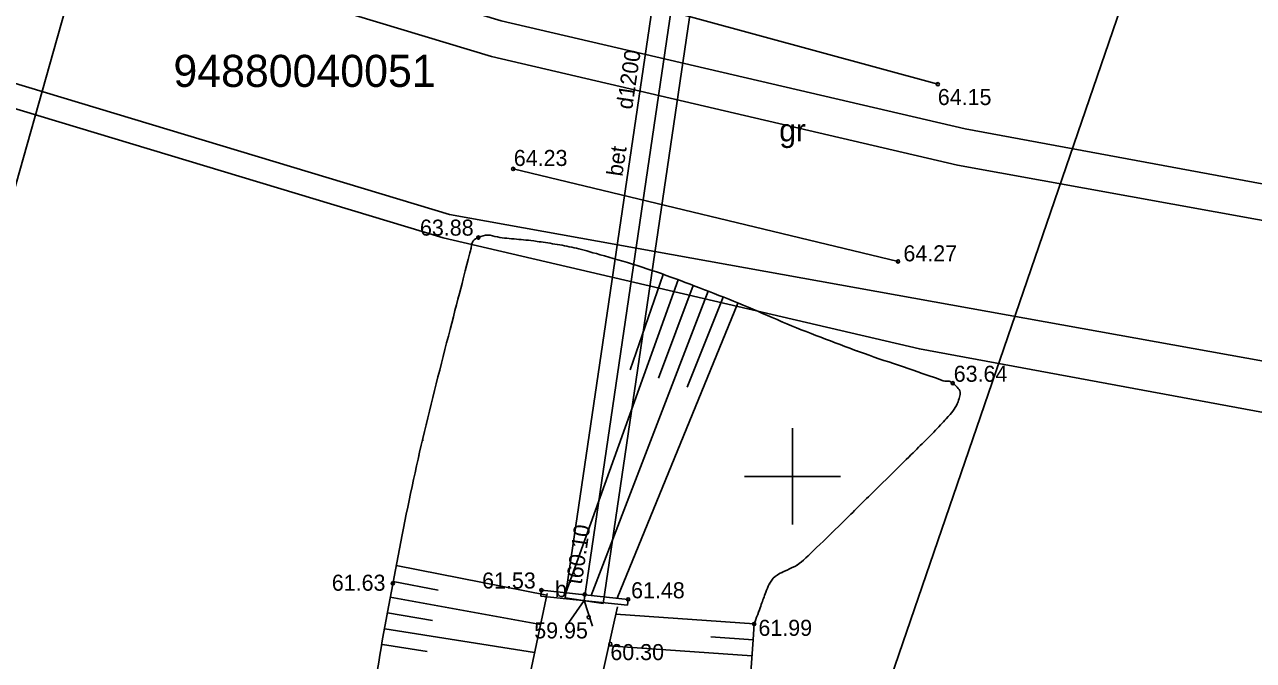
# Model space of a CAD drawing. Extents: x 616607 to 617499, y 408385 to 409695.
# Drawn here: x 617176.04 to 617214.38, y 409044.26 to 409064.08 of the extents above; entities that cross this region are included whole.
import ezdxf

# ---------------------------------------------------------------- set-up
doc = ezdxf.new("R2010")
doc.units = 0
for name, color, linetype in [('BUVE_BDET_####_####_#', 7, 'Continuous'), ('BUVE_BDET_####_TKST_#', 7, 'Continuous'), ('BUVE_INZE_VEKT_####_#', 7, 'Continuous'), ('CELI_CSEG_####_TKST_#', 7, 'Continuous'), ('CELI_TAKA_####_####_#', 7, 'Continuous'), ('GEOD_ELEM_####_####_#', 7, 'Continuous'), ('HIDG_GRAV_####_####_#', 7, 'Continuous'), ('HIDT_CAUR_####_####_#', 7, 'Continuous'), ('HIDT_CAUR_####_TKST_#', 7, 'Continuous'), ('HIDT_CAUR_KONT_####_#', 7, 'Continuous'), ('HIDT_ELEM_####_####_#', 7, 'Continuous'), ('RAMI_UZMR_####_####_#', 7, 'Continuous'), ('RELJ_AATZ_####_TKST_#', 7, 'Continuous'), ('RELJ_ELEM_####_####_#', 7, 'Continuous'), ('RELJ_NOGA_####_####_#', 7, 'Continuous'), ('ROBZ_IERR_####_####_#', 7, 'Continuous'), ('ROBZ_PROJ_####_####_#', 7, 'Continuous'), ('ROBZ_PROJ_####_TKST_#', 7, 'Continuous')]:
    doc.layers.add(name, color=color, linetype=linetype)

# ---------------------------------------------------------------- blocks, each defined once
blk = doc.blocks.new('PKT')
at = {"layer": 'RELJ_ELEM_####_####_#'}
blk.add_circle((0, 0), 0.05, dxfattribs=at)
blk = doc.blocks.new('CAURT')
at = {"layer": 'HIDT_ELEM_####_####_#'}
blk.add_lwpolyline([(0.75, -0.374), (0, 0), (0.75, 0.376)], dxfattribs=at)
blk = doc.blocks.new('KRUSTS')
at = {"layer": 'GEOD_ELEM_####_####_#'}
for p, q in [((0, 1.5), (0, 0)), ((-1.5, 0), (0, 0)), ((0, 0), (0, -1.5)), ((0, 0), (1.5, 0))]:
    blk.add_line(p, q, dxfattribs=at)

msp = doc.modelspace()

# ---------------------------------------------------------------- linework, layer by layer
at = {"layer": 'BUVE_BDET_####_####_#'}
for p, q in [((617192.148, 409046.271), (617192.167, 409046.451)), ((617192.148, 409046.271), (617194.853, 409045.986)), ((617194.853, 409045.986), (617194.872, 409046.167))]:
    msp.add_line(p, q, dxfattribs=at)
msp.add_lwpolyline([(617192.167, 409046.451), (617194.872, 409046.167)], dxfattribs=at)
at = {"layer": 'BUVE_INZE_VEKT_####_#'}
for points in [[(617176.359, 409067.385), (617190.61, 409063.088), (617205.141, 409059.702), (617231.897, 409054.857)], [(617230.443, 409050.755), (617189.294, 409058.158), (617174.515, 409062.614)]]:
    msp.add_lwpolyline(points, dxfattribs=at)
at = {"layer": 'CELI_TAKA_####_####_#'}
for points in [[(617193.303, 409065.287), (617204.53, 409062.221)], [(617203.29, 409056.699), (617191.285, 409059.581)]]:
    msp.add_lwpolyline(points, dxfattribs=at)
at = {"layer": 'HIDG_GRAV_####_####_#'}
for points in [[(617165.749, 408966.38), (617185.985, 409016.335), (617192.341, 409046.347)], [(617167.163, 408965.849), (617187.78, 409015.761), (617194.535, 409045.934)]]:
    msp.add_lwpolyline(points, dxfattribs=at)
at = {"layer": 'HIDT_CAUR_####_####_#'}
msp.add_lwpolyline([(617193.501, 409046.129), (617197.36, 409072.314)], dxfattribs=at)
at = {"layer": 'HIDT_CAUR_KONT_####_#'}
for p, q in [((617192.907, 409046.216), (617196.767, 409072.401)), ((617194.094, 409046.041), (617197.954, 409072.226))]:
    msp.add_line(p, q, dxfattribs=at)
msp.add_lwpolyline([(617192.907, 409046.216), (617194.094, 409046.041)], dxfattribs=at)
at = {"layer": 'RAMI_UZMR_####_####_#'}
msp.add_lwpolyline([(617101.571, 408748.246), (617213.472, 409074.039), (617215.883, 409140.56), (617165.121, 409241.478), (617252.137, 409353.424), (617269.572, 409425.099), (617332.631, 409510.312), (617439.945, 409622.037), (617425.373, 409635.959), (617242.079, 409440.82), (617216.614, 409355.716), (617136.613, 409246.751), (617191.828, 409115.62), (617145.545, 408952.8)], dxfattribs=at)
at = {"layer": 'RELJ_NOGA_####_####_#'}
for p, q in [((617190.611, 409057.487), (617190.611, 409057.488)), ((617190.611, 409057.487), (617190.611, 409057.486)), ((617190.128, 409057.401), (617190.128, 409057.402)), ((617190.128, 409057.401), (617190.128, 409057.401)), ((617191.106, 409057.417), (617191.106, 409057.418)), ((617191.106, 409057.417), (617191.106, 409057.417)), ((617191.604, 409057.371), (617191.604, 409057.372)), ((617191.604, 409057.371), (617191.604, 409057.37)), ((617192.1, 409057.311), (617192.1, 409057.311)), ((617192.1, 409057.311), (617192.1, 409057.311)), ((617192.594, 409057.233), (617192.594, 409057.234)), ((617192.594, 409057.233), (617192.594, 409057.232)), ((617193.085, 409057.139), (617193.085, 409057.139)), ((617193.085, 409057.139), (617193.085, 409057.138)), ((617189.934, 409056.95), (617189.933, 409056.951)), ((617189.934, 409056.95), (617189.935, 409056.95)), ((617193.572, 409057.025), (617193.571, 409057.024)), ((617193.572, 409057.025), (617193.572, 409057.026)), ((617194.054, 409056.892), (617194.053, 409056.891)), ((617194.054, 409056.892), (617194.054, 409056.892)), ((617194.533, 409056.75), (617194.533, 409056.751)), ((617194.533, 409056.75), (617194.533, 409056.749)), ((617189.808, 409056.467), (617189.808, 409056.466)), ((617189.808, 409056.467), (617189.808, 409056.467)), ((617195.011, 409056.602), (617195.011, 409056.602)), ((617195.011, 409056.602), (617195.011, 409056.602)), ((617195.486, 409056.447), (617195.486, 409056.448)), ((617195.486, 409056.447), (617195.486, 409056.446)), ((617195.959, 409056.286), (617195.96, 409056.287)), ((617189.683, 409055.982), (617189.682, 409055.983)), ((617189.683, 409055.982), (617189.684, 409055.982)), ((617196.431, 409056.12), (617192.927, 409046.371)), ((617195.959, 409056.286), (617194.937, 409053.324)), ((617196.9, 409055.947), (617195.819, 409053.063)), ((617196.431, 409056.12), (617196.431, 409056.121)), ((617196.9, 409055.947), (617196.9, 409055.948)), ((617197.368, 409055.77), (617193.722, 409046.288)), ((617197.833, 409055.587), (617196.71, 409052.785)), ((617197.368, 409055.77), (617197.368, 409055.771)), ((617197.833, 409055.587), (617197.833, 409055.587)), ((617189.558, 409055.498), (617189.559, 409055.498)), ((617189.558, 409055.498), (617189.558, 409055.498)), ((617198.296, 409055.398), (617194.527, 409046.203)), ((617198.296, 409055.398), (617198.296, 409055.399)), ((617198.758, 409055.207), (617198.758, 409055.207)), ((617198.758, 409055.207), (617198.758, 409055.207)), ((617189.434, 409055.014), (617189.433, 409055.014)), ((617189.434, 409055.014), (617189.435, 409055.014)), ((617199.219, 409055.014), (617199.22, 409055.015)), ((617199.219, 409055.014), (617199.219, 409055.013)), ((617199.681, 409054.821), (617199.68, 409054.821)), ((617199.681, 409054.821), (617199.681, 409054.821)), ((617189.311, 409054.529), (617189.312, 409054.529)), ((617189.311, 409054.529), (617189.311, 409054.529)), ((617200.143, 409054.631), (617200.142, 409054.63)), ((617200.143, 409054.631), (617200.143, 409054.631)), ((617200.607, 409054.443), (617200.606, 409054.443)), ((617200.607, 409054.443), (617200.607, 409054.444)), ((617189.189, 409054.044), (617189.188, 409054.045)), ((617189.189, 409054.044), (617189.19, 409054.044)), ((617201.072, 409054.262), (617201.073, 409054.263)), ((617201.072, 409054.262), (617201.072, 409054.261)), ((617201.541, 409054.087), (617201.541, 409054.086)), ((617201.541, 409054.087), (617201.541, 409054.087)), ((617202.01, 409053.916), (617202.011, 409053.917)), ((617202.01, 409053.916), (617202.01, 409053.915)), ((617202.482, 409053.748), (617202.482, 409053.748)), ((617202.482, 409053.748), (617202.482, 409053.748)), ((617189.068, 409053.559), (617189.069, 409053.559)), ((617189.068, 409053.559), (617189.068, 409053.559)), ((617202.954, 409053.584), (617202.953, 409053.583)), ((617202.954, 409053.584), (617202.954, 409053.584)), ((617203.426, 409053.42), (617203.426, 409053.421)), ((617203.426, 409053.42), (617203.426, 409053.42)), ((617203.899, 409053.258), (617203.899, 409053.259)), ((617203.899, 409053.258), (617203.899, 409053.257)), ((617188.949, 409053.074), (617188.948, 409053.074)), ((617188.949, 409053.074), (617188.949, 409053.074)), ((617204.372, 409053.095), (617204.372, 409053.094)), ((617204.372, 409053.095), (617204.372, 409053.095)), ((617204.851, 409052.96), (617204.852, 409052.961)), ((617204.851, 409052.96), (617204.851, 409052.959)), ((617188.83, 409052.588), (617188.83, 409052.588)), ((617188.83, 409052.588), (617188.83, 409052.588)), ((617205.204, 409052.636), (617205.203, 409052.636)), ((617205.204, 409052.636), (617205.204, 409052.636)), ((617188.713, 409052.102), (617188.712, 409052.102)), ((617188.713, 409052.102), (617188.714, 409052.102)), ((617205.075, 409052.169), (617205.074, 409052.169)), ((617205.075, 409052.169), (617205.076, 409052.168)), ((617204.772, 409051.773), (617204.772, 409051.773)), ((617204.772, 409051.773), (617204.772, 409051.772)), ((617188.597, 409051.616), (617188.597, 409051.616)), ((617188.597, 409051.616), (617188.597, 409051.616)), ((617204.428, 409051.409), (617204.428, 409051.41)), ((617204.428, 409051.409), (617204.429, 409051.409)), ((617188.483, 409051.129), (617188.482, 409051.129)), ((617188.483, 409051.129), (617188.484, 409051.129)), ((617204.078, 409051.053), (617204.078, 409051.053)), ((617204.078, 409051.053), (617204.078, 409051.053)), ((617188.37, 409050.642), (617188.371, 409050.642)), ((617188.37, 409050.642), (617188.37, 409050.642)), ((617203.723, 409050.7), (617203.723, 409050.701)), ((617203.723, 409050.7), (617203.724, 409050.699)), ((617188.26, 409050.154), (617188.259, 409050.154)), ((617188.26, 409050.154), (617188.261, 409050.154)), ((617203.368, 409050.349), (617203.368, 409050.349)), ((617203.368, 409050.349), (617203.368, 409050.348)), ((617203.012, 409049.997), (617203.011, 409049.998)), ((617203.012, 409049.997), (617203.013, 409049.997)), ((617188.151, 409049.666), (617188.151, 409049.666)), ((617188.151, 409049.666), (617188.151, 409049.666)), ((617202.656, 409049.647), (617202.655, 409049.647)), ((617202.656, 409049.647), (617202.656, 409049.646)), ((617188.044, 409049.177), (617188.043, 409049.178)), ((617188.044, 409049.177), (617188.045, 409049.177)), ((617202.299, 409049.296), (617202.299, 409049.297)), ((617202.299, 409049.296), (617202.3, 409049.295)), ((617187.94, 409048.689), (617187.939, 409048.689)), ((617187.94, 409048.689), (617187.94, 409048.688)), ((617201.942, 409048.946), (617201.942, 409048.946)), ((617201.942, 409048.946), (617201.943, 409048.945)), ((617201.228, 409048.246), (617201.228, 409048.246)), ((617201.228, 409048.246), (617201.228, 409048.245)), ((617201.585, 409048.596), (617201.585, 409048.596)), ((617201.585, 409048.596), (617201.586, 409048.595)), ((617187.837, 409048.199), (617187.836, 409048.199)), ((617187.837, 409048.199), (617187.838, 409048.199)), ((617200.871, 409047.896), (617200.87, 409047.897)), ((617200.871, 409047.896), (617200.872, 409047.895)), ((617187.737, 409047.709), (617187.737, 409047.709)), ((617187.737, 409047.709), (617187.737, 409047.709)), ((617200.512, 409047.547), (617200.512, 409047.548)), ((617200.512, 409047.547), (617200.513, 409047.547)), ((617187.639, 409047.219), (617187.638, 409047.219)), ((617187.639, 409047.219), (617192.331, 409046.3)), ((617187.639, 409047.219), (617187.64, 409047.219)), ((617200.111, 409047.251), (617200.11, 409047.252)), ((617200.111, 409047.251), (617200.111, 409047.25)), ((617187.544, 409046.728), (617188.95, 409046.458)), ((617187.544, 409046.728), (617187.544, 409046.728)), ((617187.544, 409046.728), (617187.544, 409046.728)), ((617199.693, 409046.976), (617199.693, 409046.977)), ((617199.693, 409046.976), (617199.693, 409046.976)), ((617199.321, 409046.644), (617199.32, 409046.645)), ((617199.321, 409046.644), (617199.322, 409046.644)), ((617187.453, 409046.237), (617187.452, 409046.237)), ((617187.453, 409046.237), (617192.137, 409045.383)), ((617187.453, 409046.237), (617187.454, 409046.236)), ((617199.096, 409046.201), (617199.096, 409046.201)), ((617199.096, 409046.201), (617199.096, 409046.201)), ((617187.367, 409045.744), (617188.771, 409045.506)), ((617187.367, 409045.744), (617187.367, 409045.744)), ((617187.367, 409045.744), (617187.367, 409045.744)), ((617198.803, 409045.4), (617194.484, 409045.707)), ((617198.924, 409045.732), (617198.924, 409045.732)), ((617198.924, 409045.732), (617198.925, 409045.731)), ((617187.286, 409045.251), (617187.285, 409045.251)), ((617187.286, 409045.251), (617191.952, 409044.508)), ((617187.286, 409045.251), (617187.287, 409045.25)), ((617198.768, 409044.901), (617197.449, 409044.995)), ((617187.209, 409044.756), (617187.209, 409044.757)), ((617187.209, 409044.756), (617188.603, 409044.545)), ((617187.209, 409044.756), (617187.209, 409044.756)), ((617198.732, 409044.402), (617194.263, 409044.72))]:
    msp.add_line(p, q, dxfattribs=at)
for points in [[(617164.214, 408966.743), (617164.067, 408966.559), (617163.746, 408966.808), (617163.516, 408966.861), (617163.258, 408966.92), (617163, 408966.979), (617162.742, 408967.038), (617162.506, 408967.092), (617162.27, 408967.145), (617162.033, 408967.199), (617161.839, 408967.244), (617161.499, 408967.338), (617161.53, 408967.523), (617162.076, 408970.795), (617163.848, 408974.182), (617165.139, 408977.462), (617166.432, 408980.748), (617167.724, 408984.034), (617169.019, 408987.319), (617170.314, 408990.606), (617171.612, 408993.892), (617172.906, 408997.179), (617174.2, 409000.463), (617175.346, 409003.8), (617176.537, 409007.126), (617179.936, 409016.621), (617183.209, 409026.15), (617185.744, 409035.924), (617186.657, 409039.444), (617186.852, 409043.096), (617187.532, 409046.664), (617188.191, 409050.122), (617189.04, 409053.52), (617189.932, 409056.942), (617189.98, 409057.126), (617190.012, 409057.369), (617190.199, 409057.442), (617190.492, 409057.556), (617190.793, 409057.447), (617191.088, 409057.419), (617191.386, 409057.391), (617191.684, 409057.369), (617191.981, 409057.328), (617192.587, 409057.244), (617193.186, 409057.135), (617193.777, 409056.97), (617195.009, 409056.627), (617196.209, 409056.219), (617197.396, 409055.759), (617198.619, 409055.285), (617199.811, 409054.744), (617201.035, 409054.276), (617202.236, 409053.817), (617203.458, 409053.413), (617204.671, 409052.991), (617204.777, 409052.954), (617204.889, 409052.983), (617204.996, 409052.903), (617205.146, 409052.79), (617205.251, 409052.619), (617205.213, 409052.483), (617205.152, 409052.266), (617205.006, 409052.028), (617204.832, 409051.838), (617204.408, 409051.373), (617203.987, 409050.962), (617203.555, 409050.533), (617202.561, 409049.55), (617201.563, 409048.573), (617200.565, 409047.597), (617200.116, 409047.158), (617199.367, 409046.94), (617199.151, 409046.35), (617199.035, 409046.033), (617198.919, 409045.717), (617198.803, 409045.4)], [(617198.803, 409045.4), (617198.615, 409042.755), (617198.427, 409040.111), (617198.238, 409037.467), (617197.787, 409031.121), (617196.45, 409024.852), (617194.315, 409018.79), (617192.146, 409012.632), (617189.639, 409006.739), (617186.922, 409000.869), (617184.173, 408994.931), (617181.194, 408989.114), (617178.515, 408983.149), (617177.185, 408980.188), (617175.902, 408977.208), (617174.699, 408974.191), (617174.102, 408972.692), (617173.577, 408971.168), (617173.022, 408969.656), (617172.469, 408968.151), (617172.801, 408966.435), (617171.55, 408965.074), (617170.839, 408964.299), (617169.714, 408965.108), (617168.821, 408965.3), (617168.683, 408965.329), (617168.544, 408965.359), (617168.405, 408965.389)]]:
    msp.add_open_spline(points, degree=3, dxfattribs=at)
at = {"layer": 'ROBZ_IERR_####_####_#'}
for points in [[(617233.239, 409055.706), (617229.417, 409056.382), (617205.386, 409060.826), (617190.906, 409064.2), (617176.774, 409068.461)], [(617174.244, 409061.912), (617189.1, 409057.433), (617203.955, 409053.972), (617228.171, 409049.493)]]:
    msp.add_lwpolyline(points, dxfattribs=at)
at = {"layer": 'ROBZ_PROJ_####_####_#'}
for points in [[(617175.523, 409069.057), (617176.774, 409068.461), (617190.906, 409064.2), (617205.386, 409060.826), (617229.417, 409056.382), (617232.944, 409055.758)], [(617229.56, 409049.247), (617228.171, 409049.493), (617203.955, 409053.972), (617189.1, 409057.433), (617174.244, 409061.912), (617174.192, 409061.937)]]:
    msp.add_lwpolyline(points, dxfattribs=at)

# ---------------------------------------------------------------- block references
at = {"layer": 'GEOD_ELEM_####_####_#'}
msp.add_blockref('KRUSTS', (617200, 409050), dxfattribs=at)
at = {"layer": 'HIDT_ELEM_####_####_#', "rotation": -98.38474485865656}
msp.add_blockref('CAURT', (617193.501, 409046.129), dxfattribs=at)
at = {"layer": 'RELJ_ELEM_####_####_#'}
for p in [(617204.53, 409062.221), (617191.285, 409059.581), (617190.199, 409057.442), (617203.29, 409056.699), (617204.996, 409052.903), (617187.532, 409046.664), (617192.167, 409046.451), (617193.513, 409046.318), (617194.872, 409046.167), (617193.641, 409045.608), (617198.803, 409045.4), (617194.317, 409044.774)]:
    msp.add_blockref('PKT', p, dxfattribs=at)

# ---------------------------------------------------------------- texts
at = {"layer": 'BUVE_BDET_####_TKST_#'}
msp.add_text('b', height=0.5, dxfattribs=at).set_placement((617192.59, 409046.237))
at = {"layer": 'CELI_CSEG_####_TKST_#'}
msp.add_text('gr', height=0.7, dxfattribs=at).set_placement((617199.585, 409060.437))
at = {"layer": 'HIDT_CAUR_####_TKST_#'}
for s, p in [('d1200', (617194.996, 409061.417)), ('bet', (617194.689, 409059.33)), ('t60.10', (617193.421, 409046.616))]:
    msp.add_text(s, height=0.5, rotation=81.6153, dxfattribs=at).set_placement(p)
at = {"layer": 'RELJ_AATZ_####_TKST_#'}
for s, p in [('64.15', (617204.531, 409061.572)), ('64.23', (617191.305, 409059.673)), ('63.88', (617188.378, 409057.502)), ('64.27', (617203.459, 409056.701)), ('63.64', (617205.027, 409052.948)), ('61.63', (617185.628, 409046.436)), ('61.53', (617190.316, 409046.505)), ('61.48', (617194.964, 409046.2)), ('59.95', (617191.942, 409044.949)), ('61.99', (617198.936, 409045.03)), ('60.30', (617194.317, 409044.274))]:
    msp.add_text(s, height=0.5, dxfattribs=at).set_placement(p)
at = {"layer": 'ROBZ_PROJ_####_TKST_#'}
msp.add_text('94880040051', height=1, dxfattribs=at).set_placement((617180.686, 409062.137))

doc.saveas('drawing.dxf')
